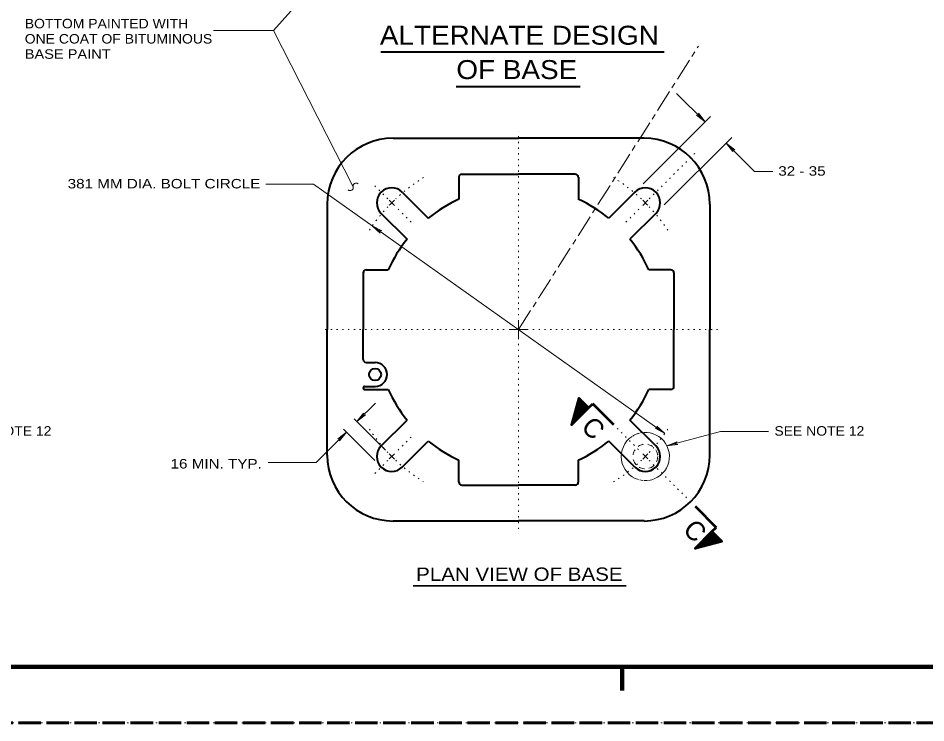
# Model space of a CAD drawing. Extents: x 312583 to 312854, y 144419 to 144597.
# Drawn here: x 312678.9 to 312751.7, y 144418.6 to 144475.1 of the extents above; entities that cross this region are included whole.
import ezdxf
from ezdxf.enums import TextEntityAlignment as Align

# ---------------------------------------------------------------- set-up
doc = ezdxf.new("R2010")
doc.units = 0
doc.header["$LTSCALE"] = 0.3
for name, pattern in [('DOTTED', [1.5, 0.3, -1.2]), ('LONG_DASH_SHORT_DASH', [9.9, 6, -1.2, 1.5, -1.2]), ('LONG_DASHED', [7.5, 6, -1.5]), ('SHORT_DASHED', [2.7, 1.5, -1.2])]:
    doc.linetypes.add(name, pattern=pattern)
for name, color, linetype, lineweight in [('1', 7, 'Continuous', 40), ('2', 7, 'Continuous', 13), ('62', 7, 'DOTTED', 13), ('63', 7, 'LONG_DASHED', 60)]:
    doc.layers.add(name, color=color, linetype=linetype, lineweight=lineweight)

msp = doc.modelspace()

# ---------------------------------------------------------------- linework, layer by layer
at = {"layer": '1', "linetype": 'LONG_DASH_SHORT_DASH', "lineweight": 13}
msp.add_line((312719.054, 144450.0929), (312733.4673, 144472.8016), dxfattribs=at)
at = {"layer": '1'}
for p, q in [((312708.9877, 144465.4263), (312719.054, 144465.4263)), ((312729.1127, 144465.4263), (312719.054, 144465.4263)), ((312714.5, 144462.5513), (312719.054, 144462.5513)), ((312723.6003, 144462.5513), (312719.054, 144462.5513)), ((312714.2623, 144462.3136), (312714.2623, 144460.5426)), ((312723.8457, 144462.3136), (312723.8457, 144460.5426)), ((312709.7313, 144461.1023), (312711.809, 144459.0246)), ((312728.369, 144461.1023), (312726.2913, 144459.0246)), ((312703.7207, 144460.1516), (312703.7207, 144450.0929)), ((312734.3873, 144460.1516), (312734.3873, 144450.0929)), ((312708.037, 144459.4079), (312710.1147, 144457.3303)), ((312730.0633, 144459.4079), (312727.9857, 144457.3303)), ((312706.5957, 144454.6469), (312706.5957, 144450.0929)), ((312706.8333, 144454.8846), (312708.5967, 144454.8846)), ((312731.267, 144454.8846), (312729.5037, 144454.8846)), ((312731.5123, 144454.6469), (312731.5123, 144450.0929)), ((312703.7207, 144440.0266), (312703.7207, 144450.0929)), ((312706.5957, 144447.6933), (312706.5957, 144450.0929)), ((312731.5123, 144445.5389), (312731.5123, 144450.0929)), ((312734.3873, 144440.0266), (312734.3873, 144450.0929)), ((312706.8333, 144447.4556), (312707.554, 144447.4556)), ((312706.7107, 144445.5389), (312707.554, 144445.5389)), ((312706.7107, 144445.3013), (312708.5967, 144445.3013)), ((312731.267, 144445.3013), (312729.5037, 144445.3013)), ((312708.037, 144440.7779), (312710.1147, 144442.8479)), ((312730.0633, 144440.7779), (312727.9857, 144442.8479)), ((312709.7313, 144439.0836), (312711.809, 144441.1536)), ((312728.369, 144439.0836), (312726.2913, 144441.1536)), ((312714.2623, 144437.8723), (312714.2623, 144439.6356)), ((312723.8457, 144437.8723), (312723.8457, 144439.6356)), ((312714.5, 144437.6346), (312719.054, 144437.6346)), ((312723.6003, 144437.6346), (312719.054, 144437.6346)), ((312708.9877, 144434.7596), (312719.054, 144434.7596)), ((312729.1127, 144434.7596), (312719.054, 144434.7596))]:
    msp.add_line(p, q, dxfattribs=at)
at = {"layer": '1', "linetype": 'DOTTED', "lineweight": 13}
for p, q in [((312729.5267, 144460.5733), (312733.3523, 144464.3913)), ((312708.5737, 144460.5733), (312707.4543, 144461.6849)), ((312710.4367, 144458.7026), (312709.2023, 144459.9446)), ((312727.6637, 144458.7026), (312728.898, 144459.9446)), ((312726.966, 144442.1809), (312728.898, 144440.2413)), ((312710.4367, 144441.4833), (312709.2023, 144440.2413)), ((312708.5737, 144439.6126), (312707.4543, 144438.4933)), ((312729.5267, 144439.6126), (312732.9613, 144436.1779))]:
    msp.add_line(p, q, dxfattribs=at)
at = {"layer": '1', "lineweight": 13}
for p, q in [((312709.095, 144460.0519), (312708.6887, 144460.4583)), ((312729.013, 144460.0519), (312729.4117, 144460.4583)), ((312709.095, 144440.1339), (312708.6887, 144439.7276)), ((312729.013, 144440.1339), (312729.4117, 144439.7276))]:
    msp.add_line(p, q, dxfattribs=at)
at = {"layer": '1', "lineweight": 158}
for p, q in [((312616.5, 144423.0846), (312849, 144423.0846)), ((312727.35, 144421.1646), (312727.35, 144423.0846))]:
    msp.add_line(p, q, dxfattribs=at)
at = {"layer": '1'}
msp.add_circle((312707.5502, 144446.4973), 0.4792, dxfattribs=at)
at = {"layer": '1', "linetype": 'SHORT_DASHED', "lineweight": 13}
msp.add_circle((312729.2143, 144439.9269), 0.9909, dxfattribs=at)
at = {"layer": '1'}
for centre, radius, start, end in [((312708.9877, 144460.1535), 5.2708, 90, 180), ((312729.1127, 144460.1535), 5.2708, 0, 90), ((312714.4981, 144462.3098), 0.2396, 90, 180), ((312723.6022, 144462.3098), 0.2396, 0, 90), ((312708.8861, 144460.2551), 1.1979, 45, 225), ((312729.2143, 144460.2551), 1.1979, 315, 135), ((312719.0502, 144450.091), 11.5, 114.62432, 129.02068), ((312719.0502, 144450.091), 11.5, 50.97932, 65.37568), ((312719.0502, 144450.091), 11.5, 140.97932, 155.37568), ((312719.0502, 144450.091), 11.5, 24.62432, 39.02068), ((312706.8314, 144454.6431), 0.2396, 90, 180), ((312731.2689, 144454.6431), 0.2396, 0, 90), ((312706.8314, 144447.6952), 0.2396, 180, 270), ((312707.5502, 144446.4973), 0.9583, 270, 90), ((312706.7116, 144445.4191), 0.1198, 89.54164, 270.45836), ((312719.0502, 144450.091), 11.5, 204.62432, 219.02068), ((312719.0502, 144450.091), 11.5, 320.97932, 335.37568), ((312731.2689, 144445.5389), 0.2396, 270, 0), ((312708.8861, 144439.9269), 1.1979, 135, 315), ((312719.0502, 144450.091), 11.5, 230.97932, 245.37568), ((312719.0502, 144450.091), 11.5, 294.62432, 309.02068), ((312729.2143, 144439.9269), 1.1979, 225, 45), ((312708.9877, 144440.0285), 5.2708, 180, 270), ((312729.1127, 144440.0285), 5.2708, 270, 0), ((312714.4981, 144437.8723), 0.2396, 180, 270), ((312723.6022, 144437.8723), 0.2396, 270, 0)]:
    msp.add_arc(centre, radius, start, end, dxfattribs=at)
at = {"layer": '1', "linetype": 'DOTTED', "lineweight": 13}
for start, end in [(121.96733, 133.24434), (46.75566, 58.03267), (136.75599, 146.30781), (33.69219, 43.24401), (213.69219, 223.24401), (316.75599, 326.30781), (226.75566, 238.03268), (301.96733, 313.24434)]:
    msp.add_arc((312719.0502, 144450.091), 14.375, start, end, dxfattribs=at)
at = {"layer": '1', "lineweight": 13}
for centre, radius, start, end in [((312719.0502, 144450.091), 14.375, 133.83351, 136.1341), ((312719.0502, 144450.091), 14.375, 43.8659, 46.16649), ((312729.2143, 144439.9269), 1.9285, 123.40478, 253.63943), ((312729.2143, 144439.9269), 1.9285, 113.4094, 121.62611), ((312729.2143, 144439.9269), 1.9285, 104.2012, 111.95028), ((312729.2143, 144439.9269), 1.9285, 277.84546, 101.24321), ((312719.0502, 144450.091), 14.375, 223.8659, 226.16649), ((312719.0502, 144450.091), 14.375, 313.83351, 316.1341), ((312729.2143, 144439.9269), 1.9285, 256.68425, 263.99995), ((312729.2143, 144439.9269), 1.9285, 266.64022, 275.48905)]:
    msp.add_arc(centre, radius, start, end, dxfattribs=at)
at = {"layer": '2'}
for p, q in [((312699.4043, 144474.0513), (312705.8827, 144481.3729)), ((312699.4043, 144474.0513), (312694.582, 144474.0513)), ((312699.4043, 144474.0513), (312705.7907, 144461.5316)), ((312734.004, 144466.7373), (312731.727, 144469.0143)), ((312729.0437, 144461.7846), (312734.4487, 144467.1819)), ((312733.314, 144467.2739), (312733.5823, 144467.1589)), ((312734.004, 144466.7373), (312733.314, 144467.2739)), ((312733.4673, 144467.4273), (312733.5823, 144467.1589)), ((312734.004, 144466.7373), (312733.4673, 144467.4273)), ((312730.738, 144460.0903), (312736.143, 144465.4876)), ((312735.6983, 144465.0429), (312737.9677, 144462.7659)), ((312735.6983, 144465.0429), (312736.235, 144464.3529)), ((312735.6983, 144465.0429), (312736.3883, 144464.5063)), ((312736.235, 144464.3529), (312736.1123, 144464.6289)), ((312736.3883, 144464.5063), (312736.1123, 144464.6289)), ((312737.9677, 144462.7659), (312739.4459, 144462.7659)), ((312702.6243, 144461.7463), (312698.791, 144461.7463)), ((312702.6243, 144461.7463), (312730.7687, 144441.7746)), ((312707.324, 144458.4113), (312707.968, 144457.8209)), ((312707.324, 144458.4113), (312708.0983, 144457.9973)), ((312707.968, 144457.8209), (312707.807, 144458.0663)), ((312708.0983, 144457.9973), (312707.807, 144458.0663)), ((312719.054, 144450.0929), (312719.054, 144450.8596)), ((312719.054, 144450.0929), (312718.2873, 144450.0929)), ((312719.054, 144450.0929), (312719.8207, 144450.0929)), ((312719.054, 144450.0929), (312719.054, 144449.3263)), ((312706.0973, 144442.7253), (312707.5847, 144444.2126)), ((312708.3743, 144440.4406), (312705.8597, 144442.9553)), ((312706.0973, 144442.7253), (312706.634, 144443.4076)), ((312706.0973, 144442.7253), (312706.7797, 144443.2619)), ((312706.634, 144443.4076), (312706.5113, 144443.1393)), ((312706.7797, 144443.2619), (312706.5113, 144443.1393)), ((312707.5233, 144439.5973), (312705.0163, 144442.1043)), ((312730.0097, 144442.1886), (312730.2933, 144442.1196)), ((312730.7687, 144441.7746), (312730.0097, 144442.1886)), ((312730.1323, 144442.3649), (312730.2933, 144442.1196)), ((312730.7687, 144441.7746), (312730.1323, 144442.3649)), ((312702.816, 144439.4439), (312705.2463, 144441.8743)), ((312705.2463, 144441.8743), (312704.5563, 144441.3376)), ((312704.5563, 144441.3376), (312704.8323, 144441.4603)), ((312705.2463, 144441.8743), (312704.7097, 144441.1843)), ((312704.7097, 144441.1843), (312704.8323, 144441.4603)), ((312730.945, 144440.7779), (312735.2537, 144441.9356)), ((312735.2537, 144441.9356), (312739.087, 144441.9356)), ((312730.945, 144440.7779), (312731.7577, 144441.1076)), ((312730.945, 144440.7779), (312731.8113, 144440.9006)), ((312731.7577, 144441.1076), (312731.5123, 144440.9313)), ((312731.8113, 144440.9006), (312731.5123, 144440.9313)), ((312702.816, 144439.4439), (312698.9827, 144439.4439))]:
    msp.add_line(p, q, dxfattribs=at)
at = {"layer": '2', "lineweight": 40}
for p, q in [((312708.0237, 144472.3416), (312730.7242, 144472.3416)), ((312714.0553, 144469.5816), (312723.9981, 144469.5816))]:
    msp.add_line(p, q, dxfattribs=at)
at = {"layer": '2', "linetype": 'DOTTED'}
for p, q in [((312719.054, 144451.2429), (312719.054, 144465.9629)), ((312717.904, 144450.0929), (312703.2453, 144450.0929)), ((312720.204, 144450.0929), (312735.0083, 144450.0929)), ((312719.054, 144448.9429), (312719.054, 144433.9853))]:
    msp.add_line(p, q, dxfattribs=at)
at = {"layer": '2', "lineweight": 35}
for p, q in [((312724.3057, 144444.1666), (312723.792, 144444.2969)), ((312724.3363, 144444.1283), (312723.792, 144444.2739)), ((312724.2673, 144444.2049), (312723.7997, 144444.3199)), ((312724.2367, 144444.2356), (312723.8073, 144444.3506)), ((312724.1983, 144444.2739), (312723.815, 144444.3659)), ((312724.1677, 144444.3046), (312723.8227, 144444.3966)), ((312724.137, 144444.3353), (312723.8303, 144444.4119)), ((312724.0987, 144444.3659), (312723.838, 144444.4426)), ((312724.0373, 144444.4349), (312723.8457, 144444.4809)), ((312724.0603, 144444.4043), (312723.8457, 144444.4579)), ((312723.93, 144444.5423), (312723.861, 144444.5499)), ((312723.9683, 144444.5039), (312723.861, 144444.5346)), ((312723.999, 144444.4733), (312723.861, 144444.5039)), ((312723.8993, 144444.5729), (312723.8763, 144444.5729)), ((312724.2367, 144443.3846), (312723.6003, 144443.5609)), ((312724.252, 144443.4076), (312723.608, 144443.5839)), ((312724.298, 144443.4459), (312723.6157, 144443.6299)), ((312724.275, 144443.4229), (312723.6157, 144443.6069)), ((312724.321, 144443.4689), (312723.6233, 144443.6529)), ((312724.3517, 144443.4996), (312723.6387, 144443.6989)), ((312724.3363, 144443.4843), (312723.6387, 144443.6759)), ((312724.367, 144443.5303), (312723.6463, 144443.7219)), ((312724.413, 144443.5609), (312723.654, 144443.7603)), ((312724.3977, 144443.5456), (312723.654, 144443.7449)), ((312724.4283, 144443.5839), (312723.6617, 144443.7909)), ((312724.4513, 144443.6069), (312723.6693, 144443.8139)), ((312724.4897, 144443.6453), (312723.677, 144443.8599)), ((312724.4667, 144443.6223), (312723.677, 144443.8369)), ((312724.5127, 144443.6683), (312723.6847, 144443.8906)), ((312724.5433, 144443.7066), (312723.6923, 144443.9289)), ((312724.528, 144443.6836), (312723.6923, 144443.9059)), ((312724.5893, 144443.7373), (312723.7077, 144443.9826)), ((312724.5663, 144443.7219), (312723.7077, 144443.9519)), ((312724.6047, 144443.7603), (312723.7153, 144443.9979)), ((312724.6277, 144443.7756), (312723.723, 144444.0209)), ((312724.643, 144443.8293), (312723.7307, 144444.0669)), ((312724.6507, 144443.7986), (312723.7307, 144444.0439)), ((312724.5817, 144443.8906), (312723.746, 144444.1129)), ((312724.6047, 144443.8676), (312723.746, 144444.0899)), ((312724.5433, 144443.9289), (312723.7613, 144444.1359)), ((312724.4743, 144443.9979), (312723.769, 144444.1819)), ((312724.505, 144443.9596), (312723.769, 144444.1666)), ((312724.4437, 144444.0286), (312723.7767, 144444.2049)), ((312724.3747, 144444.0976), (312723.7843, 144444.2586)), ((312724.4053, 144444.0669), (312723.7843, 144444.2356)), ((312723.6157, 144442.7636), (312723.3933, 144442.8173)), ((312723.631, 144442.7789), (312723.401, 144442.8479)), ((312723.6693, 144442.8173), (312723.4163, 144442.8863)), ((312723.654, 144442.8019), (312723.4163, 144442.8709)), ((312723.6923, 144442.8403), (312723.424, 144442.9093)), ((312723.7307, 144442.8786), (312723.4317, 144442.9553)), ((312723.7077, 144442.8633), (312723.4317, 144442.9399)), ((312723.746, 144442.9016), (312723.447, 144442.9859)), ((312723.7843, 144442.9399), (312723.4547, 144443.0319)), ((312723.769, 144442.9169), (312723.4547, 144443.0013)), ((312723.8227, 144442.9783), (312723.47, 144443.0703)), ((312723.8073, 144442.9629), (312723.47, 144443.0549)), ((312723.8457, 144443.0013), (312723.4777, 144443.0933)), ((312723.884, 144443.0396), (312723.4853, 144443.1469)), ((312723.861, 144443.0166), (312723.4853, 144443.1239)), ((312723.8993, 144443.0549), (312723.493, 144443.1623)), ((312723.9453, 144443.0933), (312723.5007, 144443.2159)), ((312723.9223, 144443.0703), (312723.5007, 144443.1929)), ((312723.9683, 144443.1163), (312723.5083, 144443.2389)), ((312723.9837, 144443.1316), (312723.516, 144443.2619)), ((312724.022, 144443.1699), (312723.5237, 144443.3079)), ((312723.999, 144443.1469), (312723.5237, 144443.2849)), ((312724.045, 144443.1929), (312723.539, 144443.3309)), ((312724.0833, 144443.2313), (312723.5467, 144443.3693)), ((312724.0603, 144443.2083), (312723.5467, 144443.3539)), ((312724.0987, 144443.2543), (312723.5543, 144443.3999)), ((312724.137, 144443.2926), (312723.562, 144443.4459)), ((312724.114, 144443.2696), (312723.562, 144443.4229)), ((312724.1907, 144443.3539), (312723.5773, 144443.5149)), ((312724.1753, 144443.3309), (312723.5773, 144443.4919)), ((312724.16, 144443.3156), (312723.5773, 144443.4613)), ((312724.2137, 144443.3693), (312723.6003, 144443.5379)), ((312723.3167, 144442.4646), (312723.3013, 144442.4799)), ((312723.3627, 144442.5106), (312723.3167, 144442.5183)), ((312723.3397, 144442.4876), (312723.3167, 144442.5029)), ((312723.378, 144442.5259), (312723.3243, 144442.5413)), ((312723.3933, 144442.5489), (312723.332, 144442.5719)), ((312723.4317, 144442.5873), (312723.3397, 144442.6103)), ((312723.4163, 144442.5643), (312723.3397, 144442.5873)), ((312723.4777, 144442.6333), (312723.355, 144442.6563)), ((312723.4547, 144442.6103), (312723.355, 144442.6333)), ((312723.493, 144442.6486), (312723.3627, 144442.6793)), ((312723.5083, 144442.6639), (312723.3703, 144442.7023)), ((312723.5467, 144442.7023), (312723.378, 144442.7483)), ((312723.5313, 144442.6869), (312723.378, 144442.7253)), ((312723.5697, 144442.7253), (312723.3857, 144442.7789)), ((312723.5927, 144442.7406), (312723.3933, 144442.7943)), ((312734.0193, 144433.3719), (312734.165, 144432.8199)), ((312734.0423, 144433.3949), (312734.188, 144432.8199)), ((312734.0577, 144433.4103), (312734.211, 144432.8276)), ((312734.073, 144433.4333), (312734.2417, 144432.8353)), ((312734.1037, 144433.4486), (312734.257, 144432.8353)), ((312734.1113, 144433.4639), (312734.2877, 144432.8506)), ((312734.1343, 144433.4869), (312734.3107, 144432.8506)), ((312734.1497, 144433.5023), (312734.3337, 144432.8583)), ((312734.1727, 144433.5253), (312734.3567, 144432.8659)), ((312734.1957, 144433.5483), (312734.372, 144432.8736)), ((312734.2187, 144433.5713), (312734.4027, 144432.8736)), ((312734.234, 144433.5866), (312734.4257, 144432.8889)), ((312734.2493, 144433.6019), (312734.4487, 144432.8889)), ((312734.28, 144433.6173), (312734.464, 144432.8966)), ((312734.2953, 144433.6479), (312734.4947, 144432.9043)), ((312734.3107, 144433.6633), (312734.51, 144432.9119)), ((312734.3337, 144433.6863), (312734.5407, 144432.9119)), ((312734.3567, 144433.7093), (312734.5637, 144432.9196)), ((312734.372, 144433.7246), (312734.5867, 144432.9273)), ((312734.3873, 144433.7476), (312734.6097, 144432.9273)), ((312734.4103, 144433.7629), (312734.6327, 144432.9349)), ((312734.4333, 144433.7783), (312734.6557, 144432.9503)), ((312734.4563, 144433.8013), (312734.6787, 144432.9503)), ((312734.464, 144433.8166), (312734.7017, 144432.9579)), ((312734.487, 144433.8396), (312734.7247, 144432.9656)), ((312734.5023, 144433.8549), (312734.74, 144432.9656)), ((312734.5253, 144433.8779), (312734.7707, 144432.9733)), ((312734.5483, 144433.9009), (312734.7937, 144432.9886)), ((312734.579, 144433.8933), (312734.8167, 144432.9886)), ((312734.6097, 144433.8549), (312734.8397, 144433.0039)), ((312734.6403, 144433.8319), (312734.8627, 144433.0039)), ((312734.6787, 144433.7936), (312734.8857, 144433.0116)), ((312734.7093, 144433.7629), (312734.9087, 144433.0193)), ((312734.74, 144433.7246), (312734.9317, 144433.0193)), ((312734.7783, 144433.6939), (312734.9547, 144433.0269)), ((312734.8167, 144433.6556), (312734.9853, 144433.0346)), ((312734.8473, 144433.6249), (312735.0007, 144433.0346)), ((312734.878, 144433.5943), (312735.0237, 144433.0423)), ((312734.9163, 144433.5559), (312735.0467, 144433.0423)), ((312734.947, 144433.5253), (312735.0697, 144433.0576)), ((312734.9853, 144433.4869), (312735.0927, 144433.0576)), ((312735.016, 144433.4486), (312735.1157, 144433.0653)), ((312735.0543, 144433.4179), (312735.1463, 144433.0806)), ((312735.085, 144433.3873), (312735.1617, 144433.0806)), ((312733.2987, 144432.6513), (312733.314, 144432.5823)), ((312733.314, 144432.6666), (312733.337, 144432.5899)), ((312733.337, 144432.6896), (312733.36, 144432.5976)), ((312733.3523, 144432.7049), (312733.383, 144432.6053)), ((312733.3753, 144432.7279), (312733.406, 144432.6053)), ((312733.3907, 144432.7433), (312733.429, 144432.6129)), ((312733.406, 144432.7663), (312733.452, 144432.6206)), ((312733.429, 144432.7816), (312733.475, 144432.6359)), ((312733.4443, 144432.8046), (312733.498, 144432.6359)), ((312733.4673, 144432.8199), (312733.521, 144432.6359)), ((312733.4903, 144432.8429), (312733.544, 144432.6513)), ((312733.5133, 144432.8659), (312733.567, 144432.6513)), ((312733.5287, 144432.8813), (312733.5977, 144432.6513)), ((312733.5517, 144432.9043), (312733.613, 144432.6666)), ((312733.567, 144432.9196), (312733.636, 144432.6666)), ((312733.59, 144432.9426), (312733.659, 144432.6743)), ((312733.613, 144432.9656), (312733.6897, 144432.6819)), ((312733.6283, 144432.9809), (312733.705, 144432.6896)), ((312733.6513, 144433.0039), (312733.7357, 144432.6973)), ((312733.6667, 144433.0193), (312733.751, 144432.7049)), ((312733.6897, 144433.0423), (312733.7817, 144432.7049)), ((312733.705, 144433.0576), (312733.797, 144432.7203)), ((312733.728, 144433.0806), (312733.82, 144432.7203)), ((312733.7433, 144433.0959), (312733.843, 144432.7279)), ((312733.7587, 144433.1189), (312733.8737, 144432.7356)), ((312733.7817, 144433.1343), (312733.889, 144432.7356)), ((312733.797, 144433.1496), (312733.912, 144432.7433)), ((312733.82, 144433.1726), (312733.9427, 144432.7509)), ((312733.843, 144433.1956), (312733.9657, 144432.7509)), ((312733.866, 144433.2186), (312733.981, 144432.7663)), ((312733.8813, 144433.2339), (312734.0117, 144432.7663)), ((312733.8967, 144433.2493), (312734.0347, 144432.7816)), ((312733.9197, 144433.2723), (312734.0577, 144432.7816)), ((312733.9427, 144433.2953), (312734.073, 144432.7893)), ((312733.958, 144433.3106), (312734.1037, 144432.7969)), ((312733.981, 144433.3336), (312734.119, 144432.8046)), ((312734.004, 144433.3566), (312734.1497, 144432.8046)), ((312735.1157, 144433.3566), (312735.1847, 144433.0883)), ((312735.154, 144433.3183), (312735.2077, 144433.0959)), ((312735.1847, 144433.2876), (312735.2307, 144433.0959)), ((312735.223, 144433.2493), (312735.2537, 144433.1113)), ((312735.2537, 144433.2186), (312735.2767, 144433.1189)), ((312735.292, 144433.1803), (312735.2997, 144433.1189)), ((312735.3227, 144433.1496), (312735.3227, 144433.1266)), ((312733.2143, 144432.5669), (312733.222, 144432.5593)), ((312733.2373, 144432.5899), (312733.245, 144432.5669)), ((312733.2603, 144432.6129), (312733.268, 144432.5669)), ((312733.2757, 144432.6283), (312733.291, 144432.5823)), ((312710.596, 144429.5693), (312727.6915, 144429.5693))]:
    msp.add_line(p, q, dxfattribs=at)
at = {"layer": '2', "lineweight": 53}
for p, q in [((312724.6583, 144443.8139), (312724.9957, 144444.1436)), ((312726.69, 144442.4569), (312724.9957, 144444.1436)), ((312733.2067, 144435.9403), (312734.8933, 144434.2459)), ((312734.556, 144433.9086), (312734.8933, 144434.2459))]:
    msp.add_line(p, q, dxfattribs=at)
for points in [[(312724.6583, 144443.8139), (312723.8763, 144444.5959), (312723.3013, 144442.4569)], [(312734.556, 144433.9086), (312735.3457, 144433.1266), (312733.2067, 144432.5593)]]:
    msp.add_lwpolyline(points, close=True, dxfattribs=at)
at = {"layer": '2'}
for centre, start, end in [((312706.0189, 144461.5998), 46.06269, 196.06269), ((312705.5586, 144461.4673), 226.06269, 16.06269)]:
    msp.add_arc(centre, 0.2395, start, end, dxfattribs=at)
at = {"layer": '62'}
msp.add_lwpolyline([(312601.2, 144418.5846), (312853.5, 144418.5846), (312853.5, 144596.7846)], dxfattribs=at)
at = {"layer": '63'}
msp.add_line((312851.75, 144418.5846), (312583.526, 144418.5846), dxfattribs=at)

# ---------------------------------------------------------------- texts
at = {"layer": '2'}
for s, width, p in [('BOTTOM PAINTED WITH', 1.1, (312679.4644, 144474.2359)), ('ONE COAT OF BITUMINOUS', 1.1, (312679.4644, 144473.0159)), ('BASE PAINT', 1.15, (312679.4644, 144471.7959)), ('32 - 35', 1.2, (312739.8729, 144462.4268)), ('381 MM DIA. BOLT CIRCLE', 1.2, (312682.9024, 144461.4073)), ('SEE NOTE 12', 1.1, (312674.3957, 144441.5966)), ('SEE NOTE 12', 1.1, (312739.5623, 144441.5966)), ('16 MIN. TYP.', 1.2, (312691.1537, 144438.9646))]:
    msp.add_text(s, height=0.76, dxfattribs=dict(at, width=width)).set_placement(p)
for s, height, width, p in [('ALTERNATE DESIGN', 1.52, 1.1, (312719.1149, 144472.9227)), ('OF BASE', 1.52, 1.1, (312718.9103, 144470.1703)), ('PLAN VIEW OF BASE', 1.07, 1.15, (312719.1151, 144429.9612))]:
    msp.add_text(s, height=height, dxfattribs=dict(at, width=width)).set_placement(p, align=Align.CENTER)
for height, p in [(1.534, (312724.5052, 144441.6671)), (1.533, (312732.6625, 144433.4408))]:
    msp.add_text('C', height=height, rotation=315, dxfattribs=at).set_placement(p, align=Align.CENTER)

doc.saveas('drawing.dxf')
